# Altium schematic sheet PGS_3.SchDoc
size 381 x 241 mm; SheetNumber: 1; SheetTotal: 2
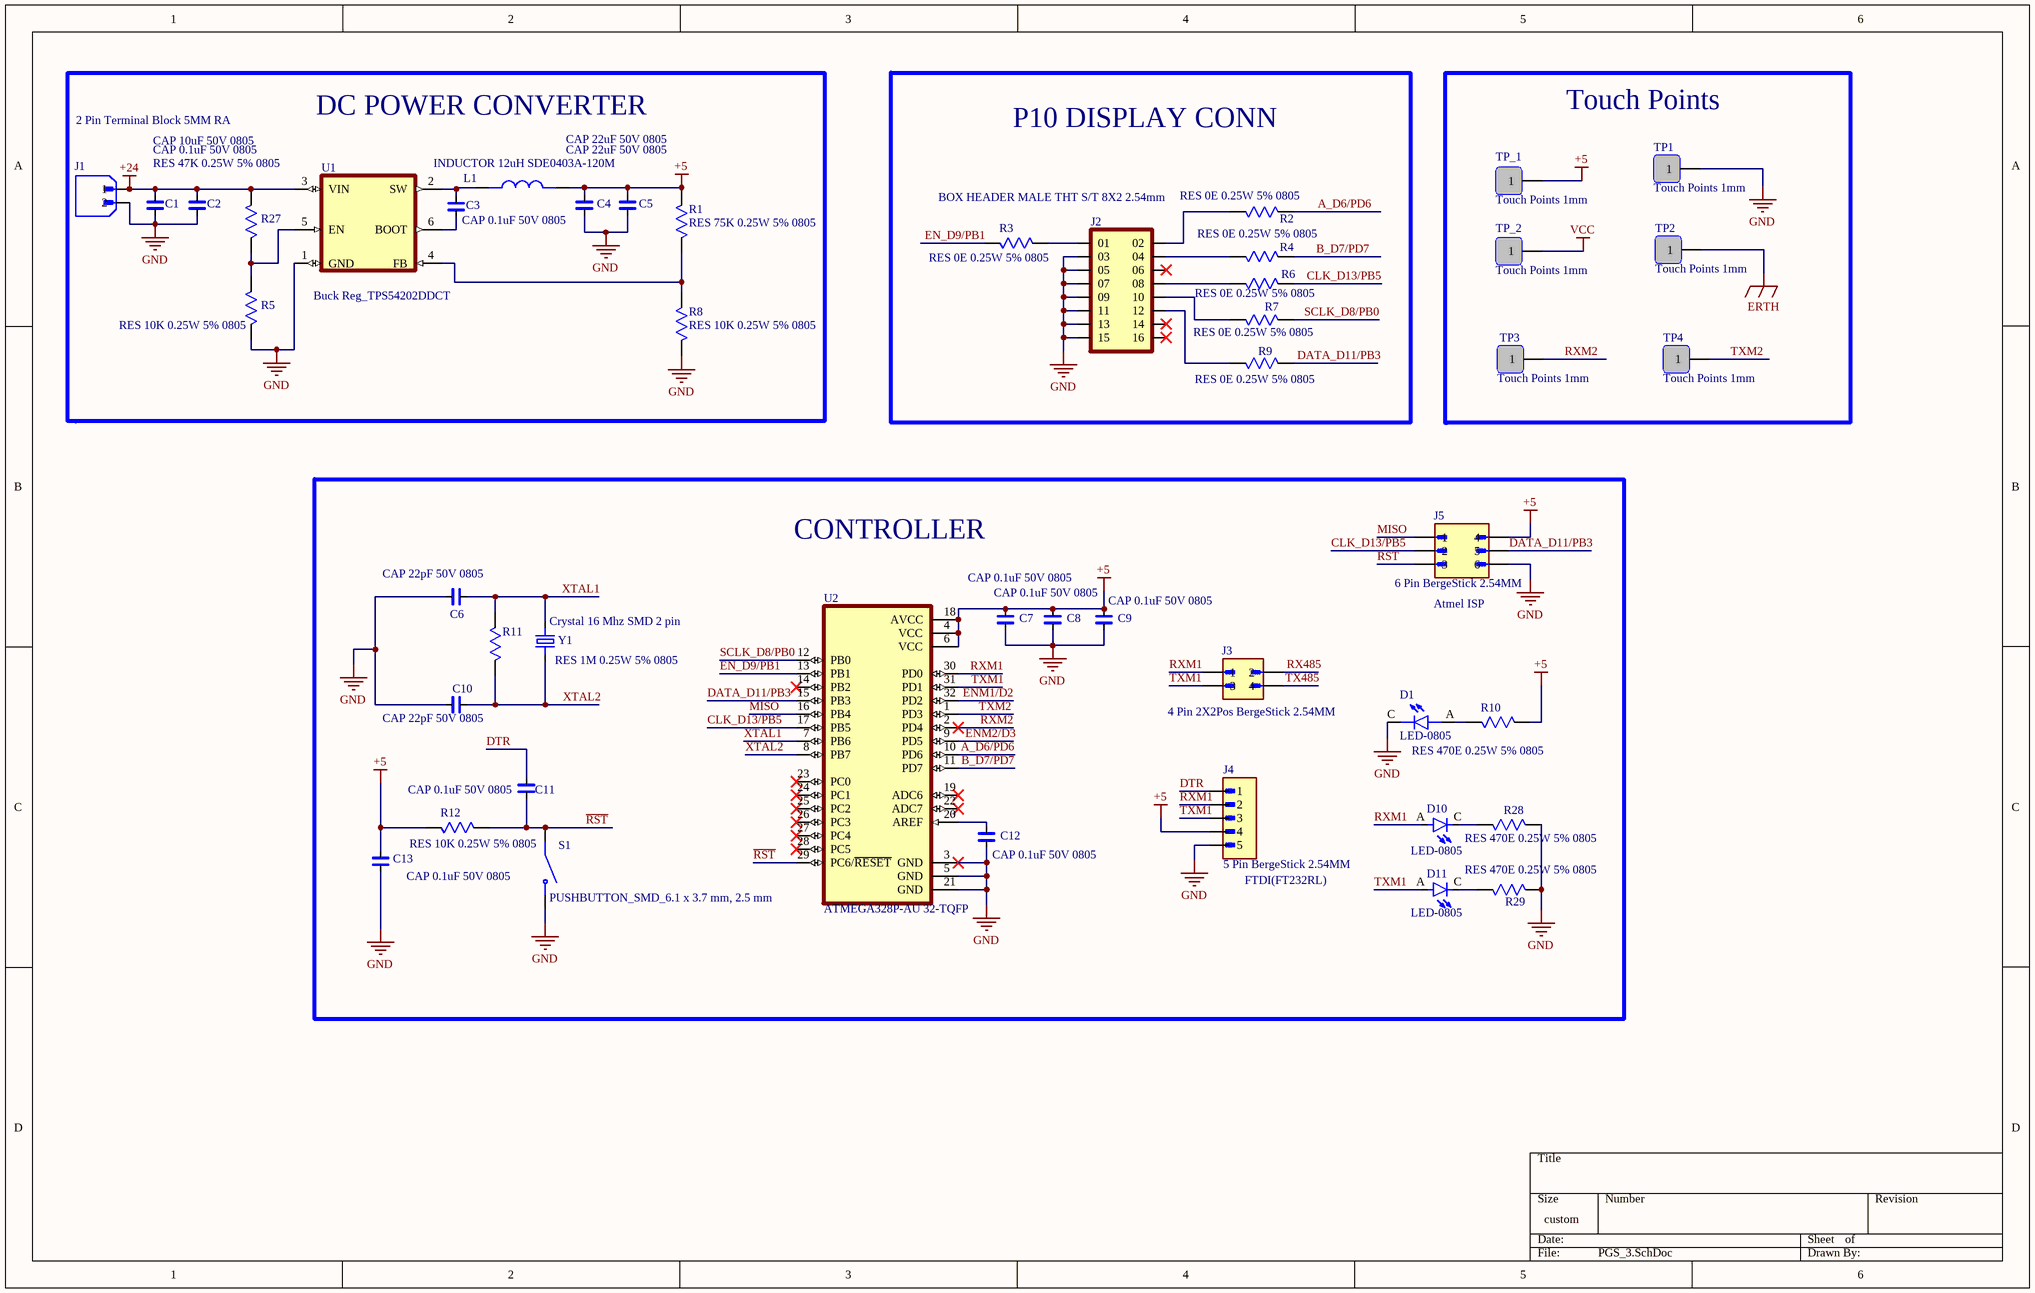
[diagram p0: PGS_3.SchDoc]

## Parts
C1  CAP 10uF 50V 0805  [CAP CER 0.1uF/50V 5%]
C2  CAP 0.1uF 50V 0805  [CAP CER 0.1uF/50V 5%]
C3  CAP 0.1uF 50V 0805  [CAP CER 0.1uF/50V 5%]
C4  CAP 22uF 50V 0805  [CAP CER 0.1uF/50V 5%]
C5  CAP 22uF 50V 0805  [CAP CER 0.1uF/50V 5%]
C6  CAP 22pF 50V 0805  [CAP CER 0.1uF/50V 5%]
C7  CAP 0.1uF 50V 0805  [CAP CER 0.1uF/50V 5%]
C8  CAP 0.1uF 50V 0805  [CAP CER 0.1uF/50V 5%]
C9  CAP 0.1uF 50V 0805  [CAP CER 0.1uF/50V 5%]
C10  CAP 22pF 50V 0805  [CAP CER 0.1uF/50V 5%]
C11  CAP 0.1uF 50V 0805  [CAP CER 0.1uF/50V 5%]
C12  CAP 0.1uF 50V 0805  [CAP CER 0.1uF/50V 5%]
C13  CAP 0.1uF 50V 0805  [CAP CER 0.1uF/50V 5%]
D1  LED-0805  [LED-0805]
D10  LED-0805  [LED-0805]
D11  LED-0805  [LED-0805]
J1  2 Pin Terminal Block 5MM RA  [2 Pin Terminal Block 5MM RA]
J2  BOX HEADER MALE THT S/T 8X2 2.54mm  [BOX HEADER MALE 8X2 2.54mm]
J3  4 Pin 2X2Pos BergeStick 2.54MM  [4 Pin BergeStick 2.54MM]
J4  5 Pin BergeStick 2.54MM  [5 Pin BergeStick 2.54MM]
J5  6 Pin BergeStick 2.54MM  [6 Pin BergeStick 2.54MM - duplicate]
L1  INDUCTOR 12uH SDE0403A-120M  [INDUCTOR 12uH SDE0403A-120M]
R1  RES 75K 0.25W 5% 0805  [RES 0805 10K/0.25W 5%]
R2  RES 0E 0.25W 5% 0805  [RES 0805 10K/0.25W 5%]
R3  RES 0E 0.25W 5% 0805  [RES 0805 10K/0.25W 5%]
R4  RES 0E 0.25W 5% 0805  [RES 0805 10K/0.25W 5%]
R5  RES 10K 0.25W 5% 0805  [RES 0805 10K/0.25W 5%]
R6  RES 0E 0.25W 5% 0805  [RES 0805 10K/0.25W 5%]
R7  RES 0E 0.25W 5% 0805  [RES 0805 10K/0.25W 5%]
R8  RES 10K 0.25W 5% 0805  [RES 0805 10K/0.25W 5%]
R9  RES 0E 0.25W 5% 0805  [RES 0805 10K/0.25W 5%]
R10  RES 470E 0.25W 5% 0805  [RES 0805 10K/0.25W 5%]
R11  RES 1M 0.25W 5% 0805  [RES 0805 10K/0.25W 5%]
R12  RES 10K 0.25W 5% 0805  [RES 0805 10K/0.25W 5%]
R27  RES 47K 0.25W 5% 0805  [RES 0805 10K/0.25W 5%]
R28  RES 470E 0.25W 5% 0805  [RES 0805 10K/0.25W 5%]
R29  RES 470E 0.25W 5% 0805  [RES 0805 10K/0.25W 5%]
S1  PUSHBUTTON_SMD_6.1 x 3.7 mm, 2.5 mm  [PUSHBUTTON_SMD_6.1 x 3.7 mm, 2.5 mm]
TP1  Touch Points 1mm  [Touch Points 1mm]
TP2  Touch Points 1mm  [Touch Points 1mm]
TP3  Touch Points 1mm  [Touch Points 1mm]
TP4  Touch Points 1mm  [Touch Points 1mm]
TP_1  Touch Points 1mm  [Touch Points 1mm]
TP_2  Touch Points 1mm  [Touch Points 1mm]
U1  Buck Reg_TPS54202DDCT  [Buck Reg_TPS54202DDCT]
U2  ATMEGA328P-AU 32-TQFP  [ATMEGA328P-AU 32-TQFP]
Y1  Crystal 16 Mhz SMD 2 pin  [Crystal 16 Mhz SMD 2 pin]

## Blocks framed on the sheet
DC POWER CONVERTER: C1-C5 J1 L1 R1 R5 R8 R27 U1
P10 DISPLAY CONN: J2 R2-R4 R6 R7 R9
Touch Points: TP1-TP4 TP_1 TP_2
CONTROLLER: C6-C13 D1 D10 D11 J3-J5 R10-R12 R28 R29 S1 U2 Y1

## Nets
+5: C4.2 C5.2 C7.2 C8.2 C9.2 C13.2 J4.4 J5.4 L1.2 R1.2 R10.2 R12.1 TP_1.1 U2.4(VCC) U2.6(VCC) U2.18(AVCC)
+24: C1.2 C2.2 J1.1 R27.2 U1.3(VIN)
ERTH: TP2.1
GND: C1.1 C2.1 C4.1 C5.1 C6.1 C7.1 C8.1 C9.1 C10.1 C12.1 C13.1 D1.C J1.2 J2.03 J2.05 J2.07 J2.09 J2.11 J2.13 J2.15 J4.5 J5.6 R5.1 R8.1 R28.2 R29.2 S1.2 TP1.1 U1.1(GND) U2.3(GND) U2.5(GND) U2.21(GND)
VCC: TP_2.1
A_D6/PD6: R2.2 U2.10(PD6)
B_D7/PD7: R4.2 U2.11(PD7)
CLK_D13/PB5: J5.2 R6.2 U2.17(PB5)
DATA_D11/PB3: J5.5 R9.2 U2.15(PB3)
DTR: C11.2 J4.1
EN_D9/PB1: R3.1 U2.13(PB1)
ENM1/D2: U2.32(PD2)
ENM2/D3: U2.9(PD5)
MISO: J5.1 U2.16(PB4)
~{RST}: C11.1 J5.3 R12.2 S1.1 U2.29(PC6/~{RESET})
RX485: J3.2
RXM1: D10.A J3.1 J4.2 U2.30(PD0)
RXM2: TP3.1 U2.2(PD4)
SCLK_D8/PB0: R7.2 U2.12(PB0)
TX485: J3.4
TXM1: D11.A J3.3 J4.3 U2.31(PD1)
TXM2: TP4.1 U2.1(PD3)
XTAL1: C6.2 R11.2 U2.7(PB6) Y1.2
XTAL2: C10.2 R11.1 U2.8(PB7) Y1.1
NetC3_1: C3.1 U1.6(BOOT)
NetC3_2: C3.2 L1.1 U1.2(SW)
NetC12_2: C12.2 U2.20(AREF)
NetD1_A: D1.A R10.1
NetD10_C: D10.C R28.1
NetD11_C: D11.C R29.1
NetJ2_01: J2.01 R3.2
NetJ2_02: J2.02 R2.1
NetJ2_04: J2.04 R4.1
NetJ2_08: J2.08 R6.1
NetJ2_10: J2.10 R7.1
NetJ2_12: J2.12 R9.1
NetR1_1: R1.1 R8.2 U1.4(FB)
NetR5_2: R5.2 R27.1 U1.5(EN)

Not connected (* = marked no-connect by the designer): J2 06* 14* 16*; U2 14(PB2)* 19(ADC6)* 22(ADC7)* 23(PC0)* 24(PC1)* 25(PC2)* 26(PC3)* 27(PC4)* 28(PC5)*

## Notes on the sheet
- (near J5) Atmel ISP
- (near J4) FTDI(FT232RL)

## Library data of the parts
C1-C13 = CAP CER 0.1uF/50V 5%: CAP CER 0.1uF/50V  Ceramic Capacitor X7R 0805 (2012 Metric); MF: Samsung; MP: CL21B104KCFNNNE
D1 = LED-0805: Red 640nm LED Indication - Discrete 1.85V 0805 (2012 Metric) APT2012SRCPRV; MF: Kingbright
D10 D11 = LED-0805: Red 640nm LED Indication - Discrete 1.85V 0805 (2012 Metric) SMT APT2012SRCPRV; MF: Kingbright
J1 = 2 Pin Terminal Block 5MM RA: 2 Pin Terminal Block HDR 5MM THT RA _OQ0271510000G; MF: Amphenol Anytek
J2 = BOX HEADER MALE THT S/T 8X2 2.54mm: THT BOX HEADER MALE S/T 8X2 2.54mm 16 pin; MP: TSS-108-01-T-D
J3 = 4 Pin 2X2Pos BergeStick 2.54MM: 4 Pin 2X2Pos THT S/T BergeStick 2.54MM Amphenol 67997-104HLF 3A; MF: Amphenol ICC
J4 = 5 Pin BergeStick 2.54MM: 5 Pin 5Pos THT S/T BergeStick 2.54MM Amphenol68002-405HLF 3A
J5 = 6 Pin BergeStick 2.54MM_1: 6 Pin 3X3Pos THT S/T BergeStick 2.54MM Amphenol 69192-406HLF; MF: AMPHENOL ICC / FCI
L1 = INDUCTOR 12uH SDE0403A-120M: INDUCTOR_2020(5.5mmX4.5mm)  SMT INDUCTOR 12uH SDE0403A-120M0 LQH5BPB4R7NT0L
R1-R12 R27 = RES 10K 0.25W 5% 0805: RESISTOR, THICK FILM, 10K, 5%, 0805 0.25W; MP: ERJ-6GEYJ103V; MF: Panasonic Electronic
R28 R29 = RES 10K 0.25W 5% 0805: RESISTOR, THICK FILM, 10K, 5%, 0805 0.25W SMT; MP: ERJ-6GEYJ103V; MF: Panasonic Electronic
S1 = PUSHBUTTON_SMD_6.1 x 3.7 mm, 2.5 mm: 6.1 x 3.7 mm, 2.5 mm Actuator Height, 260 gf, Red, Surface Mount, SPST, Tactile Switch, TS09-63-25-R-260-SMT-TR; MF: Same Sky
TP1-TP4 TP_1 TP_2 = Touch Points: Touch Points 0.75mm to1mm
U1 = TPS54202DDCT: 4.5V to 28V Input, 2A Output, EMI Friendly Synchronous Step-Down Converter TPS54202DDCT; MF: Texas Instruments
U2 = ATMEGA328P-AU_1: AVR AVRÂ® ATmega Microcontroller IC 8-Bit 20MHz 32KB (16K x 16) FLASH 32-TQFP (7x7); MF: Microchip
Y1 = Crystal 16 Mhz SMD 2 pin_1: 16 MHz Â±30ppm Crystal 20pF 60 Ohms HC-49/US FOXSDLF/128-20 16 Mhz Crystal SMD –CSM-4ALX(28ALX) 12.5mmX4.85mmX4mm; MF: Fox Electronics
